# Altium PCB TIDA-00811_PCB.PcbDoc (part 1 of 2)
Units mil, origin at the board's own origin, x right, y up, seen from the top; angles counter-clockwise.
Board outline 3346.46 x 1968.5 mil, 2 copper layers (Top Layer, Bottom Layer), stack 62 mil thick; 221 components, 100 nets, 529 pads, 192 vias.
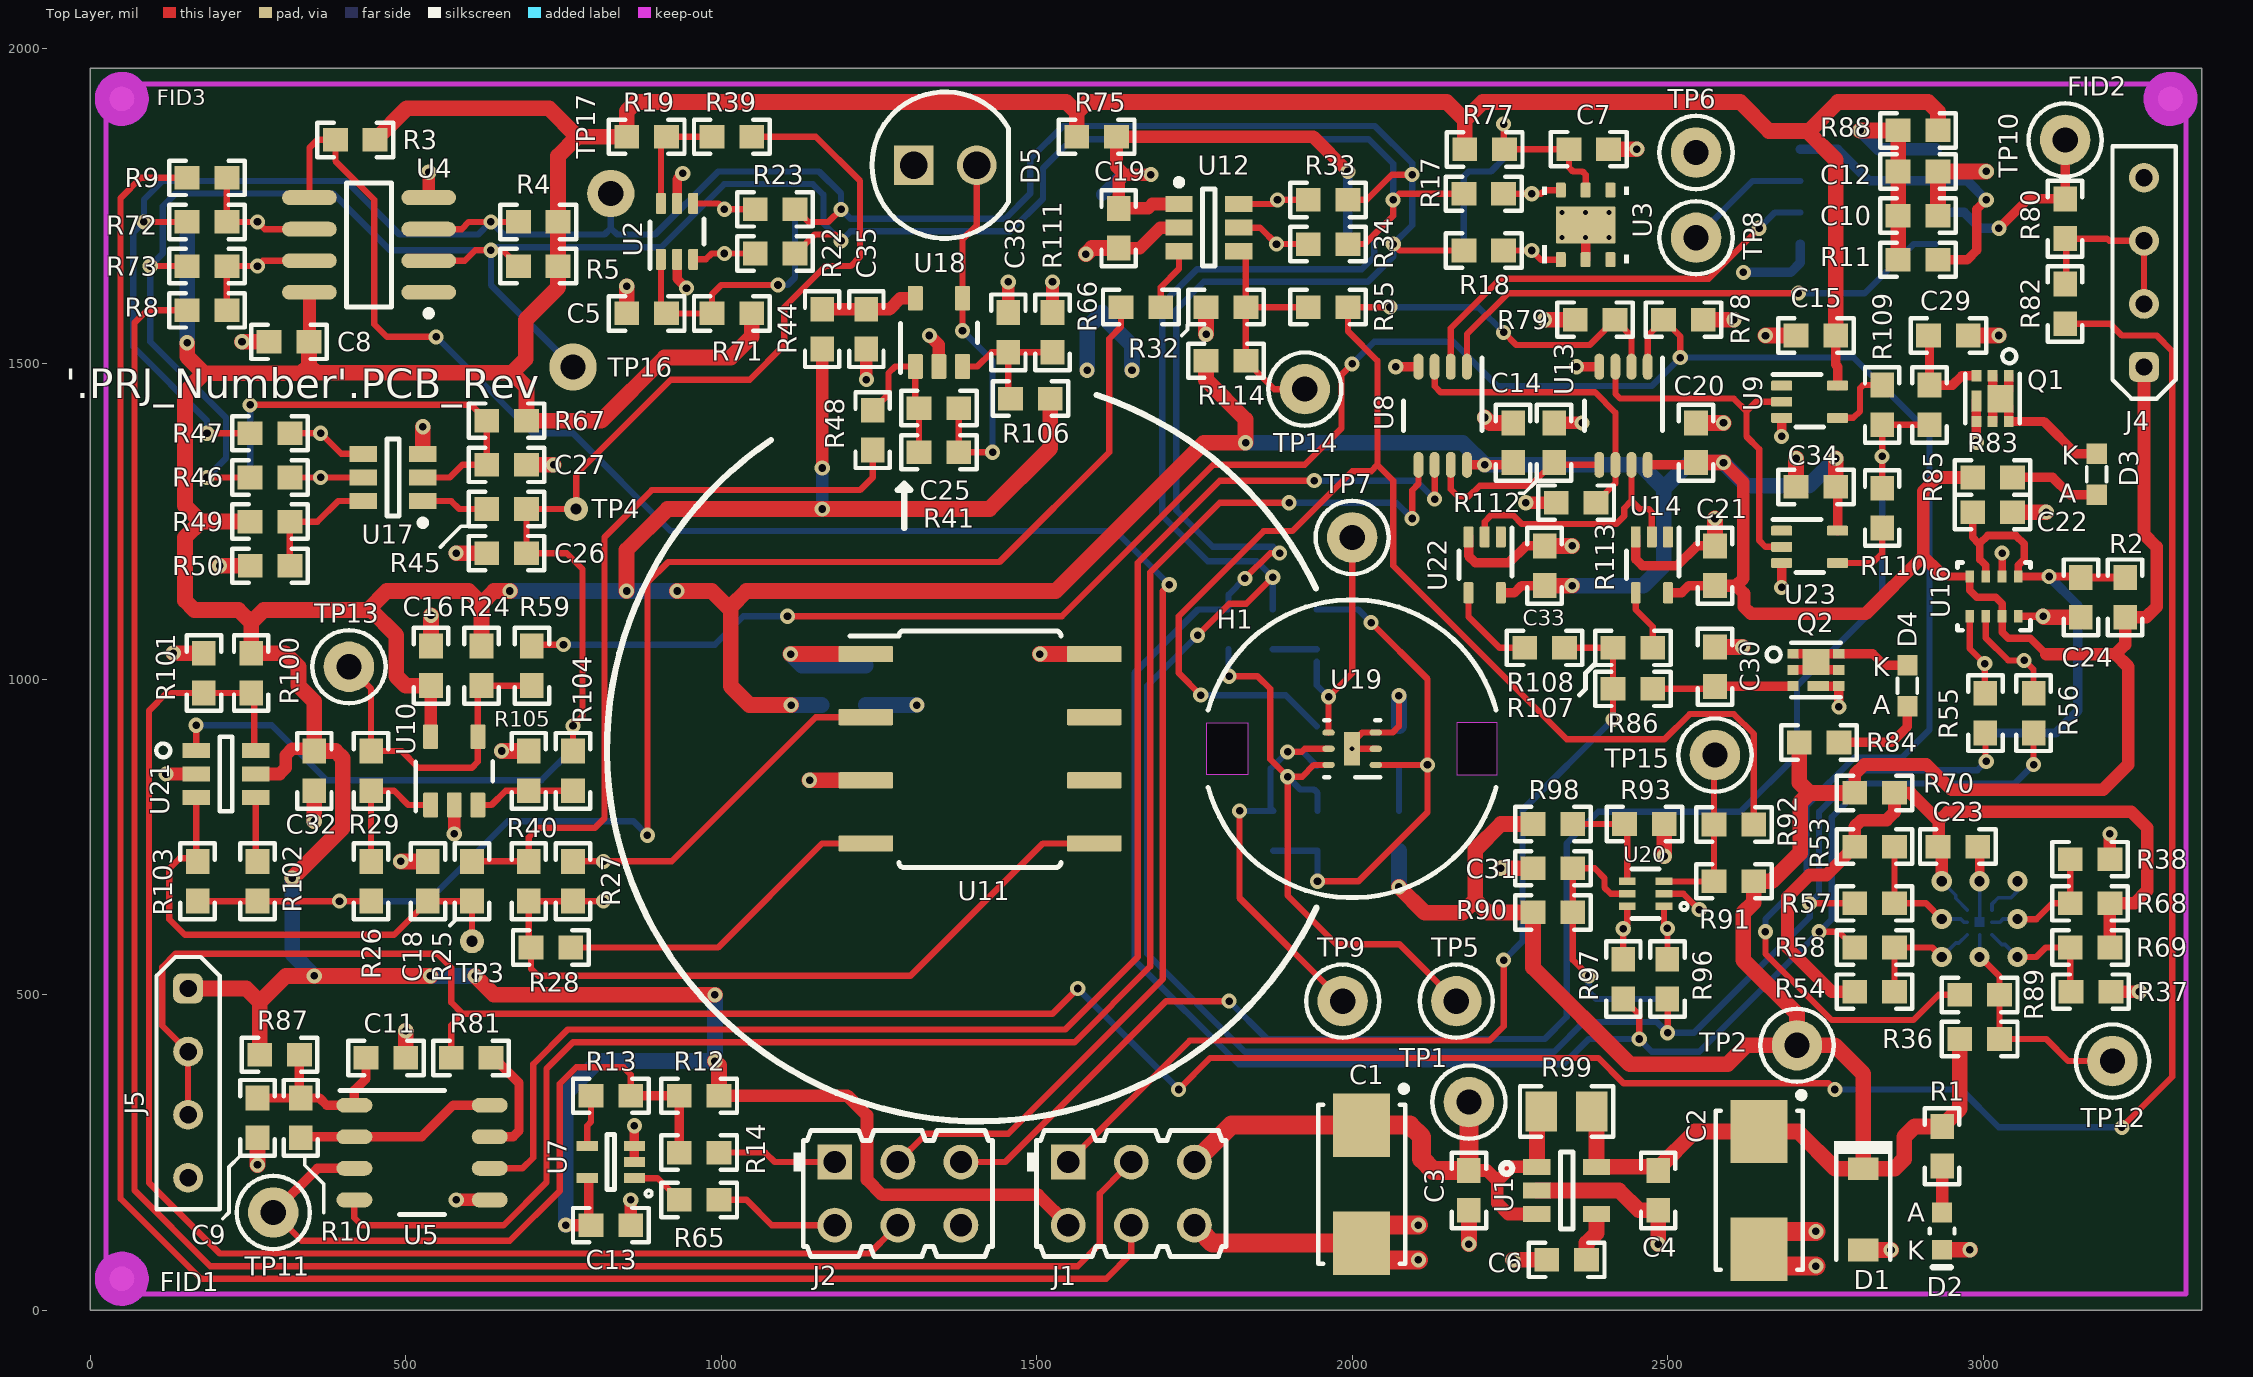
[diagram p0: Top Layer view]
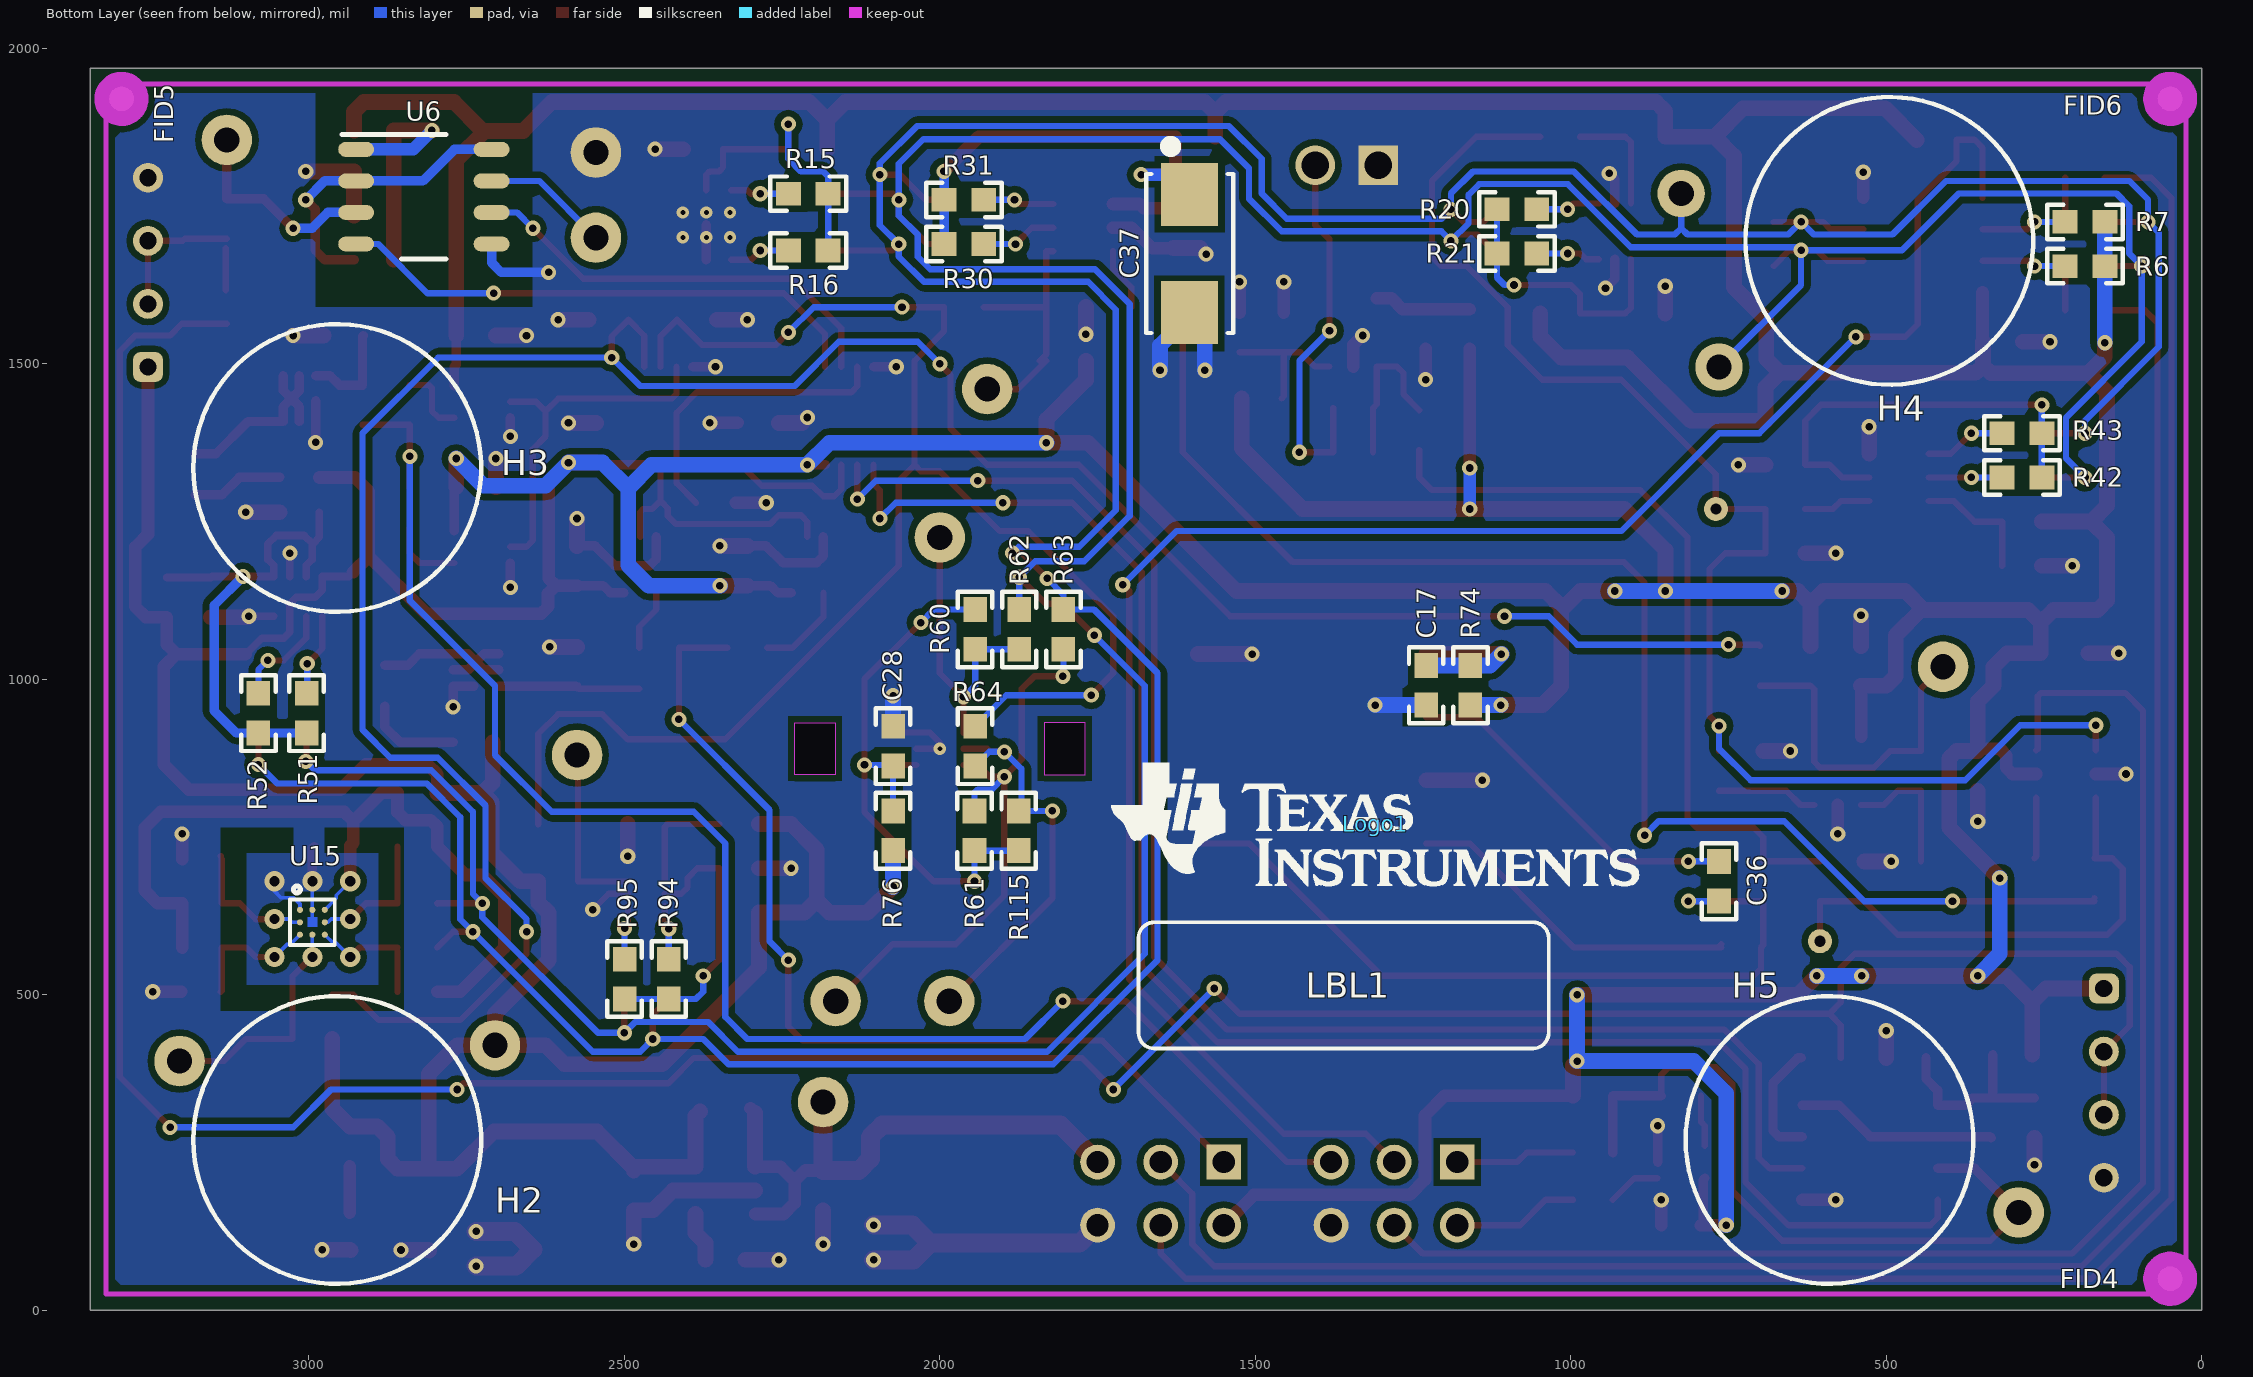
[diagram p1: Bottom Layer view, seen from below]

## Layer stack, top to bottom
Top Solder: solder mask 0.4, Solder Resist, Dk 3.5
Top Layer: signal copper 1.4
Dielectric1: core 59.2, FR-4 High Tg, Dk 4.8
Bottom Layer: signal copper 1.4
Bottom Solder: solder mask 0.4, Solder Resist, Dk 3.5

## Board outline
0,0 0,1968.5 3346.46,1968.5 3346.46,0

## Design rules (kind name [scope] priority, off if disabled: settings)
AcuteAngle [All] p1: minimum=4.50000000000000E+0001 checktracksonly=FALSE
AssemblyTestPointUsage [All] p1: valid=2
Clearance Clearance_1 [All] p1: gap=10 except(7.87: SMDPad-SMDPad)
Clearance Clearance_Trace [inpolygon vs istrack] p2: gap=15 except(7.87: SMDPad-SMDPad)
Clearance Clearance_Poly [InPolygon] p3: gap=25 except(15: Track-Poly Via-Poly)
Clearance [All] p4: gap=7.87
ComponentClearance ComponentClearance_MountingHoles_FiducialMarks [InComponentClass('Mounting Holes') vs InComponentClass('FiducialMark')] p1: gap=50 collisioncheckmode=3 verticalgap=10 showdistances=FALSE
ComponentClearance ComponentClearance_Shunt [InComponentClass('Header') vs InComponentClass('Shunt')] p2: gap=0 collisioncheckmode=3 verticalgap=0 showdistances=FALSE
ComponentClearance ComponentClearance_Logo [InComponentClass('Logo')] p3: gap=50 collisioncheckmode=3 verticalgap=10 showdistances=FALSE
ComponentClearance ComponentClearance_ScrewToNut [(HasFootprint('NY PMS 440 0025 PH')) vs (HasFootprint('Keystone_1902C'))] p4: gap=5 collisioncheckmode=3 verticalgap=10 showdistances=FALSE
ComponentClearance ComponentClearance_MountingHoles [InComponentClass('Mounting Holes')] p5: gap=250 collisioncheckmode=3 verticalgap=100000 showdistances=FALSE
ComponentClearance ComponentClearance_SmallPassives [HasFootprint('0201*') or HasFootprint('0402*') or HasFootprint('0508') or HasFootprint('0603*') or HasFootprint('0612') or HasFootprint('0805*') or HasFootprint('0815*') or HasFootprint('0830*') or HasFootprint('1206*') or HasFootprint('1210*') or HasFootprint('1808*') or HasFootprint('1812*') or HasFootprint('1825*') or HasFootprint('2010*') or HasFootprint('2220*') or HasFootprint('2225*') or HasFootprint('2512*') or HasFootprint('2728*') or HasFootprint('3518*') vs HasFootprint('0201*') or HasFootprint('0402*') or HasFootprint('0508') or HasFootprint('0603*') or HasFootprint('0612') or HasFootprint('0805*') or HasFootprint('0815*') or HasFootprint('0830*') or HasFootprint('1206*') or HasFootprint('1210*') or HasFootprint('1808*') or HasFootprint('1812*') or HasFootprint('1825*') or HasFootprint('2010*') or HasFootprint('2220*') or HasFootprint('2225*') or HasFootprint('2512*') or HasFootprint('2728*') or HasFootprint('3518*')] p6: gap=14.96 collisioncheckmode=3 verticalgap=10 showdistances=FALSE
ComponentClearance ComponentClearance_THtoSMT [IsThruComponent vs IsSMTComponent] p7: gap=40 collisioncheckmode=3 verticalgap=30 showdistances=FALSE
ComponentClearance ComponentClearance_THtoTH [IsThruComponent vs IsThruComponent] p8: gap=30 collisioncheckmode=3 verticalgap=30 showdistances=FALSE
ComponentClearance [All] p9: gap=30 collisioncheckmode=3 verticalgap=10 showdistances=FALSE
DiffPairsRouting [All] p1: maxlimit=100 minlimit=10 mostfreqgap=10 toplayer_minwidth=15 toplayer_maxwidth=15 toplayer_prefwidth=15 bottomlayer_minwidth=15 bottomlayer_maxwidth=15 bottomlayer_prefwidth=15 maxuncoupledlength=1000
FabricationTestPointUsage TestPointUsage [All] p1: valid=2 allowmultiple=FALSE
FabricationTestpoint Testpoint [All] p1: side=3 testpointundercomponent=TRUE minsize=40 maxsize=100 preferedsize=60 minholesize=0 maxholesize=40 preferedholesize=32 testpointgrid=1 allowsidetop=TRUE allowsidebottom=TRUE usegrid=TRUE gridtolerance=0.01
FanoutControl Fanout_LCC [IsLCC] p1: bgadir=Out bgaviamode=Centered fanoutstyle=Auto fanoutdirection=Alternating viagrid=1 // Fanout_LCC (Default Rule)
FanoutControl Fanout_BGA [IsBGA] p2: bgadir=Out bgaviamode=Centered fanoutstyle=Auto fanoutdirection=Alternating viagrid=1 // Fanout_BGA (Default Rule)
FanoutControl Fanout_Default [All] p4: bgadir=Out bgaviamode=Centered fanoutstyle=Auto fanoutdirection=Alternating viagrid=1 // Fanout_Default (Default Rule)
FanoutControl Fanout_Small [(CompPinCount < 5)] p5: bgadir=Out bgaviamode=Centered fanoutstyle=Auto fanoutdirection=OutThenIn viagrid=1 // Fanout_Small (Default Rule)
HoleSize [All] p1: absolutevalues=TRUE maxlimit=251 minlimit=7.87 maxpercent=80.000 minpercent=20.000
MinimumAnnularRing MinimumAnnularRing_ThermalPadVias [IsVia and InAnyComponent] p1: minimumring=5.91
MinimumAnnularRing [All] p2: minimumring=6
MinimumSolderMaskSliver MinimumSolderMaskSliver_Logo [InComponentClass('Logo') vs InComponentClass('Logo')] p1: minsoldermaskwidth=0.7
MinimumSolderMaskSliver [All] p2: minsoldermaskwidth=3
PlaneConnect [All] p1: planeconnectstyle=Relief reliefexpansion=10 reliefentries=4 reliefconductorwidth=10 reliefairgap=10
PolygonConnect [All] p1: connectstyle=Direct reliefconductorwidth=10 reliefentries=4 polygonreliefangle="90 Angle" airgapwidth=10
RoutingVias ThermalPadVias [IsVia and InAnyComponent] p1: holewidth=7.87 width=19.68 viastyle="Through Hole" minholewidth=7.87 minwidth=19.68 maxholewidth=12.99 maxwidth=23.62
RoutingVias [All] p2: holewidth=12 width=24 viastyle="Through Hole" minholewidth=12 minwidth=24 maxholewidth=20 maxwidth=40
SilkToSilkClearance SilkToSilkClearance_Pb-FreeLogo [(HasFootprint('Pb-Free_Overlay_Medium') OR HasFootprint('Pb-Free_Overlay_Small')) vs (HasFootprint('Pb-Free_Overlay_Medium') OR HasFootprint('Pb-Free_Overlay_Small'))] p1: silktosilkclearance=0
SilkToSilkClearance [All] p2: silktosilkclearance=1
SilkToSolderMaskClearance SilkToComponentPadClearance [IsPad and InAnycomponent] p1: minsilkscreentomaskgap=5 clearancetoexposedcopper=TRUE
SilkToSolderMaskClearance "Silk to Solder Mask Opening" [IsPad] p2: minsilkscreentomaskgap=4 clearancetoexposedcopper=TRUE
SolderMaskExpansion [All] p1: expansion=1.97
Width [All] p1: maxlimit=100 minlimit=6 preferedwidth=10 checkconnectedcopper=TRUE
16 further rules are at their usual default settings.

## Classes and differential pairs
component class TIDA-00811_Pg6: C9 C10 C11 C12 C13 C14 C15 C22 C24 C29 C34 D3 J4 J5 Q1 R2 R10 R11 R12 R13 R14 R51 R52 R55 R56 R65 R80 R81 R82 R83 R85 R87 R88 R109 R110 R112 R113 TP8 TP10 TP11 U5 U6 U7 U8 U9 U16 U23
component class Logo: Logo1
component class TIDA-00811_Pg7_EVM_Hardware: FID1 FID2 FID3 FID4 FID5 FID6 H1 H2 H3 H4 H5 LBL1 Logo1 ZZ1 ZZ2 ZZ3 ZZ4
component class FiducialMark: FID1 FID2 FID3 FID4 FID5 FID6
component class AssemblyNote: ZZ1 ZZ2 ZZ3 ZZ4
component class Label: LBL1
component class Header: J1 J2 J4 J5
component class TIDA-00811_Pg4: C5 C8 C16 C17 C18 C19 C25 C26 C27 C32 C35 C36 C37 C38 D5 J1 J2 R3 R4 R5 R6 R7 R8 R9 R19 R20 R21 R22 R23 R24 R25 R26 R27 R28 R29 R30 R31 R32 R33 R34 R35 R39 R40 R41 R42 R43 R44 R45 R46 R47 R48 R49 R50 R59 R66 R67 R71 R72 R73 R74 R75 R100 R101 R102 R103 R104 R105 R106 R111 R114 TP3 TP4 TP13 TP14 TP16 TP17 U2 U4 U10 U11 U12 U17 U18 U21
component class TIDA-00811_Pg5: C1 C2 C3 C4 C6 C7 C20 C21 C23 C28 C30 C31 C33 D1 D2 D4 Q2 R1 R15 R16 R17 R18 R36 R37 R38 R53 R54 R57 R58 R60 R61 R62 R63 R64 R68 R69 R70 R76 R77 R78 R79 R84 R86 R89 R90 R91 R92 R93 R94 R95 R96 R97 R98 R99 R107 R108 R115 TP1 TP2 TP5 TP6 TP7 TP9 TP12 TP15 U1 U3 U13 U14 U15 U19 U20 U22

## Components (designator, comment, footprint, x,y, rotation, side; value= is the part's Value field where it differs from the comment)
C1 "293D106X9025C2TE3" 6032-28 2015,200 r270 top
C2 "293D106X9025C2TE3" 6032-28 2645,190 r270 top
C3 "06033C104JAT2A" 0603#1 2185,190 r90 top
C4 "06033C104JAT2A" 0603#2 2485,190 r270 top
C5 "06033C104JAT2A" 0603#2 881.85,1580 r0 top
C6 "C1608C0G1E103J080AA" 0603#2 2340,80 r180 top
C7 "06033C104JAT2A" 0603#2 2375,1840.32 r180 top
C8 "06033C104JAT2A" 0603#2 315,1535 r180 top
C9 "06033C104JAT2A" 0603#2 265,305 r270 top
C10 "06033C104JAT2A" 0603#2 2896.85,1735 r0 top
C11 "06033C104JAT2A" 0603#2 468.5,400 r180 top
C12 "06033C104JAT2A" 0603#2 2896.85,1805 r180 top
C13 "06033C104JAT2A" 0603#2 825,135 r180 top
C14 "06033C104JAT2A" 0603#2 2255,1375 r270 top
C15 "06033C104JAT2A" 0603#2 2735,1544.93 r0 top
C16 "06033C104JAT2A" 0603#2 540,1021.5 r270 top
C17 "06033C104JAT2A" 0603#2 1229.09,990.67 r90 bottom
C18 "C1608C0G1E103J080AA" 0603#2 535,680 r270 top
C19 "06033C104JAT2A" 0603#2 1630,1715 r90 top
C20 "06033C104JAT2A" 0603#2 2545,1375 r270 top
C21 "06033C104JAT2A" 0603#2 2575,1180 r270 top
C22 "06033C104JAT2A" 0603#2 3015,1265 r180 top
C23 "06033C104JAT2A" 0603#2 2960,735 r180 top
C24 "06033C104JAT2A" 0603#2 3155,1130 r90 top
C25 "06035A2R7CAT2A" 0603#2 1345,1430 r0 top
C26 "C1608C0G1E103J080AA" 0603#2 659.84,1200 r0 top
C27 "" 0603#2 659.84,1340 r0 top
C28 "06033C104JAT2A" 0603#2 2074.09,894.17 r270 bottom
C29 "06033C104JAT2A" 0603#2 2945,1545 r0 top
C30 "06033C104JAT2A" 0603#2 2575,1020 r90 top
C31 "06033C104JAT2A" 0603#2 2318.15,700.62 r0 top
C32 "" 0603#2 355,855 r270 top
C33 "06033C104JAT2A" 0603#2 2305,1180 r270 top
C34 "06033C104JAT2A" 0603#2 2735,1305 r0 top
C35 "06033C104JAT2A" 0603#2 1230,1555 r90 top
C36 "GRM1885C1H560JA01D" 0603#2 765,680 r90 bottom
C37 "293D106X9025C2TE3" 6032-28 1604,1675 r270 bottom
C38 "C0603C105K4PACTU" 0603#2 1455,1550 r90 top
D1 "MMSZ5227B-7-F" SOD-123 2810,160 r270 top
D2 "LG L29K-G2J1-24-Z" "LG L29K_GREEN" 2935,125.47 r270 top
D3 "LED_LG L29K-G2J1-24-Z" LED0603AA 3180,1325 r270 top
D4 "LED_LG L29K-G2J1-24-Z" LED0603AA 2880,990 r270 top
D5 "SFH 213" SFH_213 1355,1815 r0 top
FID1 "Fiducial" Fiducial10-20 50,50 r0 top
FID2 "Fiducial" Fiducial10-20 3296.85,1920 r0 top
FID3 "Fiducial" Fiducial10-20 50,1920 r0 top
FID4 "Fiducial" Fiducial10-20 50,50 r180 bottom
FID5 "Fiducial" Fiducial10-20 3296.85,1920 r180 bottom
FID6 "Fiducial" Fiducial10-20 50,1920 r180 bottom
H1 "IML-0669" Murata_IML-0669 2000,890 r0 top
H2 "SJ-5303 (CLEAR)" Bumpon_SJ5003Transparent#1 2955,270 r180 bottom locked
H3 "SJ-5303 (CLEAR)" Bumpon_SJ5003Transparent#1 2955,1335 r180 bottom locked
H4 "SJ-5303 (CLEAR)" Bumpon_SJ5003Transparent#1 495,1695 r180 bottom
H5 "SJ-5303 (CLEAR)" Bumpon_SJ5003Transparent#2 1140,270 r180 bottom
J1 "61300621121" Mill-Max_802-10-006-10-001000 1650,185 r0 top
J2 "61300621121" Mill-Max_802-10-006-10-001000 1280,185 r0 top
J4 "61300411121" Mill-Max_342-xx-104-00-592000 3255,1645 r90 top
J5 "61300411121" Mill-Max_342-xx-104-00-592000 155,360 r270 top
LBL1 "Size: 0.65\" x 0.20 \"" Label_650x200 1360,515 r180 bottom
Logo1 "Texas Instruments" TI_Stacked_Overlay_Small 1310,770 r180 bottom
Q1 "CSD17571Q2" SON_CSD17571Q2 3015,1445 r180 top
Q2 "CSD17571Q2" SON_CSD17571Q2 2735,1015 r270 top
R1 "RC0603FR-071KL" 0603#2 2935,260 r90 top
R2 "RC0603JR-070RL" 0603#2 3225,1130 r90 top
R3 "RC0603FR-074K7L" 0603#2 420,1855 r0 top
R4 "RC0603FR-074K7L" 0603#2 710,1725 r0 top
R5 "RC0603FR-074K7L" 0603#2 710,1655 r0 top
R6 "RC0603FR-074K7L" 0603#2 185,1655 r180 bottom
R7 "RC0603FR-074K7L" 0603#2 185,1725 r180 bottom
R8 "CRCW060310R0FKEA" 0603#2 185,1585 r180 top
R9 "CRCW060310R0FKEA" 0603#2 185,1795 r180 top
R10 "RC0603JR-070RL" 0603#2 333.5,305 r270 top
R11 "RC0603JR-070RL" 0603#2 2896.85,1665 r0 top
R12 "RC0603FR-073K3L" 0603#2 965,340 r0 top
R13 "RC0603FR-07100RL" 0603#2 825,340 r0 top
R14 "RC0603FR-07100RL" 0603#2 965,250 r180 top
R15 "RC0603FR-074K7L" 0603#2 2208.5,1769.68 r180 bottom
R16 "RC0603FR-074K7L" 0603#2 2208.5,1679.68 r180 bottom
R17 "CRCW060310R0FKEA" 0603#2 2208.5,1769.68 r180 top
R18 "CRCW060310R0FKEA" 0603#2 2208.5,1679.68 r180 top
R19 "RC0603FR-074K7L" 0603#2 881.85,1860 r0 top
R20 "RC0603FR-074K7L" 0603#2 1085.35,1745 r0 bottom
R21 "RC0603FR-074K7L" 0603#2 1085.35,1675 r0 bottom
R22 "CRCW060310R0FKEA" 0603#2 1085.35,1674.93 r0 top
R23 "CRCW060310R0FKEA" 0603#2 1085.35,1744.93 r0 top
R24 "RC0603FR-074K7L" 0603#2 620,1021.5 r90 top
R25 "CRCW0603100RFKEA" 0603#2 605,680 r270 top
R26 "CRCW060310K0FKEA" 0603#2 445,680 r90 top
R27 "RC0603FR-0747KL" 0603#2 765,680 r270 top
R28 "RC0603JR-070RL" 0603#2 730,575 r0 top
R29 "CRCW06031M00FKEA" 0603#2 445,855 r90 top
R30 "RC0603FR-074K7L" 0603#2 1961.85,1690 r0 bottom
R31 "RC0603FR-074K7L" 0603#2 1961.85,1760 r0 bottom
R32 "RC0603JR-070RL" 0603#2 1800,1590 r180 top
R33 "CRCW060310R0FKEA" 0603#2 1961.85,1759.93 r0 top
R34 "CRCW060310R0FKEA" 0603#2 1961.85,1689.93 r0 top
R35 "RC0603JR-070RL" 0603#2 1961.85,1590 r0 top
R36 "RC0603JR-072K2L" 0603#2 2994.51,429.97 r180 top
R37 "RC0603JR-070RL" 0603#2 3171,504.97 r180 top
R38 "RC0603JR-070RL" 0603#2 3169.51,714.97 r180 top
R39 "RC0603JR-070RL" 0603#2 1016.85,1860 r0 top
R40 "RC0603JR-070RL" 0603#2 695,680 r90 top
R41 "RG1608P-5362-B-T5" 0603#2 1345,1360 r180 top
R42 "RC0603FR-074K7L" 0603#2 284.84,1320 r180 bottom
R43 "RC0603FR-074K7L" 0603#2 284.84,1390 r180 bottom
R44 "RC0603JR-070RL" 0603#2 1160,1555 r270 top
R45 "RC0603JR-070RL" 0603#2 659.84,1270 r0 top
R46 "CRCW060310R0FKEA" 0603#2 284.84,1320 r0 top
R47 "CRCW060310R0FKEA" 0603#2 284.84,1390 r0 top
R48 "RC0603JR-070RL" 0603#2 1240,1395 r270 top
R49 "RC0603FR-074K7L" 0603#2 284.84,1250 r0 top
R50 "RC0603JR-070RL" 0603#2 285,1180 r0 top
R51 "RC0603FR-074K7L" 0603#2 3003.63,946.5 r270 bottom
R52 "RC0603FR-074K7L" 0603#2 3080,946.5 r270 bottom
R53 "RC0603FR-074K7L" 0603#2 2828.01,735 r180 top
R54 "RC0603FR-074K7L" 0603#2 2828.01,504.97 r180 top
R55 "CRCW060310R0FKEA" 0603#2 3003.63,946.5 r90 top
R56 "CRCW060310R0FKEA" 0603#2 3080,946.5 r90 top
R57 "CRCW060310R0FKEA" 0603#2 2828.01,644.97 r0 top
R58 "CRCW060310R0FKEA" 0603#2 2828.01,574.97 r0 top
R59 "RC0603JR-070RL" 0603#2 700,1021.5 r90 top
R60 "RC0603FR-074K7L" 0603#2 1944.09,1079.17 r90 bottom
R61 "RC0603FR-074K7L" 0603#2 1945,760 r270 bottom
R62 "CRCW060310R0FKEA" 0603#2 1874.09,1079.17 r90 bottom
R63 "CRCW060310R0FKEA" 0603#2 1804.09,1079.17 r90 bottom
R64 "RC0603JR-070RL" 0603#2 1944.09,894.17 r90 bottom
R65 "RC0603JR-070RL" 0603#2 965,175 r0 top
R66 "RC0603JR-070RL" 0603#2 1665,1590 r180 top
R67 "RC0603JR-070RL" 0603#2 659.84,1410 r0 top
R68 "RC0603FR-074K7L" 0603#2 3169.51,644.97 r0 top
R69 "RC0603FR-074K7L" 0603#2 3169.51,574.97 r0 top
R70 "RC0603JR-070RL" 0603#2 2828.01,820 r180 top
R71 "RC0603JR-070RL" 0603#2 1016.85,1580 r0 top
R72 "RC0603JR-070RL" 0603#2 185,1725 r180 top
R73 "RC0603JR-070RL" 0603#2 185,1655 r180 top
R74 "RC0603JR-070RL" 0603#2 1159.09,990.67 r270 bottom
R75 "RC0603JR-070RL" 0603#2 1595,1860 r180 top
R76 "RC0603JR-070RL" 0603#2 2074.09,760 r270 bottom
R77 "RC0603JR-070RL" 0603#2 2210,1840 r180 top
R78 "RC0603FR-074K7L" 0603#2 2525,1570 r0 top
R79 "RC0603FR-074K7L" 0603#2 2385,1570.07 r180 top
R80 "RC0603JR-070RL" 0603#2 3130,1730 r90 top
R81 "RC0603JR-070RL" 0603#2 603.5,400 r180 top
R82 "RC0603JR-070RL" 0603#2 3130,1595 r90 top
R83 "CRCW0603300RJNEA" 0603#2 3015,1320 r180 top
R84 "CRCW0603300RJNEA" 0603#2 2740,900 r180 top
R85 "CRCW0603300RJNEA" 0603#2 2915,1435 r90 top
R86 "CRCW0603300RJNEA" 0603#2 2445,985 r0 top
R87 "RC0603JR-070RL" 0603#2 300,405 r0 top
R88 "RC0603JR-070RL" 0603#2 2896.85,1870 r180 top
R89 "RC0603JR-070RL" 0603#2 2994.51,499.97 r180 top
R90 "RC0603JR-070RL" 0603#2 2318.15,630.68 r180 top
R91 "CRCW060310K0JNEA" 0603#2 2605,680 r0 top
R92 "RC0603JR-070RL" 0603#2 2605,770 r0 top
R93 "RC0603JR-070RL" 0603#2 2463.15,770.68 r0 top
R94 "RC0603FR-074K7L" 0603#2 2429.65,525 r270 bottom
R95 "RC0603FR-074K7L" 0603#2 2499.65,525 r270 bottom
R96 "CRCW060310R0FKEA" 0603#2 2499.65,525 r270 top
R97 "CRCW060310R0FKEA" 0603#2 2429.65,525 r270 top
R98 "RC0603FR-074K7L" 0603#2 2318.15,770.75 r180 top
R99 "CRCW08050000Z0EA" 0805_HV 2340,315 r0 top
R100 "RC0603FR-074K7L" 0603#2 255,1010 r270 top
R101 "RC0603FR-074K7L" 0603#2 180,1010 r270 top
R102 "ERJ-3GEY0R00V" 0603#2 265,680 r90 top
R103 "ERJ-3GEY0R00V" 0603#2 170,680 r270 top
R104 "CRCW0603300RJNEA" 0603#2 765.07,855 r90 top
R105 "CRCW060310K0FKEA" 0603#2 695,855 r90 top
R106 "CRCW060313K7FKEA" 0603#2 1490,1445 r180 top
R107 "RC0603JR-070RL" 0603#2 2445,1050 r180 top
R108 "RC0603JR-070RL" 0603#2 2305,1050 r0 top
R109 "RC0603JR-070RL" 0603#2 2840,1435 r270 top
R110 "RC0603JR-070RL" 0603#2 2840.07,1271.5 r90 top
R111 "RC0603FR-07280RL" 0603#2 1525,1550 r270 top
R112 "RC0603JR-070RL" 0603#2 2320,1375 r90 top
R113 "RC0603JR-070RL" 0603#2 2355,1280 r0 top
R114 "RC0603FR-074K7L" 0603#2 1800,1505 r180 top
R115 "RC0603FR-074K7L" 0603#2 1875,760 r270 bottom
TP1 "5000" Keystone5000 2185,330 r0 top
TP2 "5000" Keystone5000 2705,420 r0 top
TP3 "TESTPOINT" TP_H045P075 605,585 r0 top
TP4 "TESTPOINT" TP_H045P075 770,1270 r270 top
TP5 "5000" Keystone5000 2165,490 r0 top
TP6 "5000" Keystone5000 2545,1835 r0 top
TP7 "5000" Keystone5000 2000,1225 r0 top
TP8 "5000" Keystone5000 2545,1700 r0 top
TP9 "5000" Keystone5000 1985,490 r0 top
TP10 "5000" Keystone5000 3130,1855 r0 top
TP11 "5000" Keystone5000 290,155 r0 top
TP12 "5000" Keystone5000 3205,395 r0 top
TP13 "5000" Keystone5000 410,1020 r0 top
TP14 "5000" Keystone5000 1925,1460 r0 top
TP15 "5000" Keystone5000 2575,880 r0 top
TP16 "TP-5001-BLACK" TH-40 765,1495 r270 top
TP17 "TP-5001-BLACK" TH-40 825,1770 r90 top
U1 "LP2985-33DBVR" DBV0005A_N#1 2340,190 r0 top
U2 "TPL0401A-10DCKR" DCK0006A_N 930,1710 r90 top
U3 "HDC1080DMBR" DMB0006A 2370,1720.32 r90 top
U4 "PCA9515ADR" D0008A_N#1 441.85,1688.5 r180 top
U5 "TMP107BIDR" D0008A_N#2 525.79,250 r0 top
U6 "TMP107BIDR" D0008A_N#2 2817.72,1765 r180 bottom
U7 "SN74LVC1G125DCKR" DCK0005A_N#1 825,235 r180 top
U8 "SN74LVC2G32DCTR" DCT0008A_N 2143.46,1417.76 r270 top
U9 "SN74LVC1G14DCKR" DCK0005A_N#2 2725,1440 r0 top
U10 "LMV331IDBVR" DBV0005A_N#2 576.85,855 r90 top
U11 "OPT101P-J" DTL0008A_N 1410.2,890 r0 top
U12 "ADC101C021CIMK/NOPB" MK06A_N 1772.76,1715.98 r0 top
U13 "SN74LVC2G32DCTR" DCT0008A_N 2430,1417.76 r270 top
U14 "SN74LVC1G14DCKR" DCK0005A_N#2 2475,1181.5 r270 top
U15 "TMP007AIYZFR" YZF0008AEAE 2994.51,614.97 r180 bottom
U16 "BMP280" LGA8-2X2_5MM_0_65 3017.2,1131.5 r180 top
U17 "DAC101C081CIMK" MK06A_N 479.84,1320 r180 top
U18 "OPA320AIDBVR" DBV0005A_N#2 1345,1550 r90 top
U19 "OPT3001DNPT" DNP0006A 2000,890 r180 top
U20 "TMP102AIDRLT" DRL0006A_N 2465,660 r180 top
U21 "SN74LVC1G3157DBVR" SOT23-6 215,850 r0 top
U22 "SN74LVC1G17DCKR" DCK0005A_N#2 2210,1181.5 r270 top
U23 "SN74LVC1G17DCKR" DCK0005A_N#2 2725,1210 r0 top
ZZ1 "This Assembly Note is for PCB labels only" AssemblyNoteLabel -48.15,2846 r0 top
ZZ2 "These assemblies are ESD sensitive, ESD precautions shall be observed." AssemblyNote -48.15,2737.11 r0 top
ZZ3 "These assemblies must be clean and free from flux and all contaminants. Use of no clean flux is not acceptable." AssemblyNote -48.15,2648.56 r0 top
ZZ4 "These assemblies must comply with workmanship standards IPC-A-610 Class 2, unless otherwise specified." AssemblyNote -48.15,2560 r0 top

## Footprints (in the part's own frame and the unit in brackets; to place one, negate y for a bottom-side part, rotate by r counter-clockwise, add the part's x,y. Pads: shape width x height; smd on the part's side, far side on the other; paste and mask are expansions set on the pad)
0603#1 [mm] "0603 from SM-752 data"
  rect 1x0.95 smd: 1(0.8,0) 2(-0.8,0)
  silkscreen extent -1.52,-0.69 1.52,0.69, body extent -0.87,-0.47 0.87,0.47, height 1
0603#2 [mm] "0603 from SM-752 data"
  rect 1x0.95 smd: 1(-0.8,0) 2(0.8,0)
  silkscreen extent -1.52,-0.69 1.52,0.69, body extent -0.87,-0.47 0.87,0.47, height 1
0805_HV [mil] "0805 with 30mil clearance between pads"
  rect 50x63 smd: 1(-40,0) 2(40,0)
  silkscreen extent -74,-40 74,40, body extent -43,-29 43,29, height 57
6032-28 [mm] "Medium Density IPC based on Vishay Sprague 293D datasheet."
  rect 2.55x2.3 smd: 1(-2.375,0) 2(2.375,0)
  silkscreen extent -3.96,-1.75 3.2,1.83, body extent -3.15,-1.75 3.15,1.75, height 2.8
AssemblyNote [mil] "Assembly Note"
AssemblyNoteLabel [mil] "Assembly Note for PCB Labels"
Bumpon_SJ5003Transparent#1 [mil] "3M Hemispherical Bumpon transparent"
  round 1 on Mech4: 0(0,0)
  silkscreen extent -228,-228 228,228, body extent -219,-218 219,218, height 197
Bumpon_SJ5003Transparent#2 [mil] "3M Hemispherical Bumpon transparent"
  round 1 on Mech4: 0(550,0)
  silkscreen extent 322,-228 778,228, body extent 331,-218 769,218, height 197
D0008A_N#1 [mm] "SOIC, 8-Leads, Body 4.9x3.9mm, Pitch 1.27mm, IPC Medium Density"
  oval 2.2x0.6 smd: 1(-2.4,1.905) 2(-2.4,0.635) 3(-2.4,-0.635) 4(-2.4,-1.905) 5(2.4,-1.905) 6(2.4,-0.635) 7(2.4,0.635) 8(2.4,1.905)
  silkscreen extent -2.53,-2.5 0.9,2.88, body extent -2,-2.5 2,2.5, height 1.75
D0008A_N#2 [mm] "SOIC, 8-Leads, Body 4.9x3.9mm, Pitch 1.27mm, IPC Medium Density"
  oval 1.45x0.6 smd: 1(-2.725,1.905) 2(-2.725,0.635) 3(-2.725,-0.635) 4(-2.725,-1.905) 5(2.725,-1.905) 6(2.725,-0.635) 7(2.725,0.635) 8(2.725,1.905)
  silkscreen extent -3.3,-2.5 0.9,2.5, body extent -3,-2.45 3,2.45, height 1.63
DBV0005A_N#1 [mm] "SOT23, 5-Leads, Body 2.9x1.6mm, Pitch 0.95mm, Lead Span 2.8mm, IPC Medium Density"
  rect 1.1x0.65 smd: 1(-1.2,0.95) 2(-1.2,0) 3(-1.2,-0.95) 4(1.2,-0.95) 5(1.2,0.95)
  silkscreen extent -0.25,-1.55 0.25,1.55, body extent -1.42,-1.46 1.42,1.46, height 1.08
DBV0005A_N#2 [mm] "SOT23, 5-Leads, Body 2.9x1.6mm, Pitch 0.95mm, Lead Span 2.8mm, IPC Medium Density"
  rrect17% 1x0.6 smd: 1(-1.375,0.95) 2(-1.375,0) 3(-1.375,-0.95) 4(1.375,-0.95) 5(1.375,0.95)
  silkscreen extent -1.63,-1.55 0.38,1.55, body extent -1.42,-1.46 1.42,1.46, height 1.09
DCK0005A_N#1 [mm] "SOT353, 5-Leads, Body 2x1.3mm, Pitch 0.65mm, Lead Span 2.1mm, IPC Medium Density"
  rect 0.85x0.4 smd: 1(-0.95,0.65) 2(-0.95,0) 3(-0.95,-0.65) 4(0.95,-0.65) 5(0.95,0.65)
  silkscreen extent -0.15,-1.1 0.15,1.1, body extent -1.14,-1 1.14,1, height 0.94
DCK0005A_N#2 [mm] "SOT353, 5-Leads, Body 2x1.3mm, Pitch 0.65mm, Lead Span 2.1mm, IPC Medium Density"
  rrect25% 0.85x0.4 smd: 1(-1.125,0.65) 2(-1.125,0) 3(-1.125,-0.65) 4(1.125,-0.65) 5(1.125,0.65)
  silkscreen extent -1.48,-1.02 0.55,1.1, body extent -1.14,-1 1.14,1, height 0.95
DCK0006A_N [mm] "SOT23, 6-Leads, Body 2x1.3mm, Pitch 0.65mm, Lead Span 2.1mm, IPC Medium Density"
  rrect25% 0.85x0.4 smd: 1(-1.125,0.65) 2(-1.125,0) 3(-1.125,-0.65) 4(1.125,-0.65) 5(1.125,0) 6(1.125,0.65)
  silkscreen extent -1.5,-1.09 0.51,1.09, body extent -1.14,-1 1.14,1, height 0.95
DCT0008A_N [mm] "TSOP, 8-Leads, Body 3x2.8mm, Pitch 0.65mm, IPC Medium Density"
  oval 1.05x0.4 smd: 1(-1.975,0.975) 2(-1.975,0.325) 3(-1.975,-0.325) 4(-1.975,-0.975) 5(1.975,-0.975) 6(1.975,-0.325) 7(1.975,0.325) 8(1.975,0.975)
  silkscreen extent -2.32,-1.57 0.6,1.58, body extent -2.01,-1.47 2.01,1.48, height 1.3
DMB0006A [mm] "TI"
  rrect25% 0.6x0.4 smd: 1(-1.4,1) 2(-1.4,0) 3(-1.4,-1) 4(1.4,-1) 5(1.4,0) 6(1.4,1)
  rrect7% 1.5x2.4 smd paste-0.75: 7(0,0)
  silkscreen extent -1.55,-1.75 1.55,1.75, body extent -1.5,-1.5 1.5,1.5, height 0.81
DNP0006A [mm] "DFN-6 2x2mm"
  oval 0.5x0.25 smd: 1(-0.95,0.65) 2(-0.95,0) 3(-0.95,-0.655) 4(0.95,-0.65) 5(0.95,0) 6(0.95,0.65)
  rect 0.65x1.35 smd paste-0.5: 7(0,0)
  silkscreen extent -1.12,-1.15 1.12,1.15, body extent -1,-1 1,1, height 0.64
DRL0006A_N [mm] "SOTFL, 6-Flat Leads, Body 1.2x1.6x0.6mm, Pitch 0.5mm, IPC Medium Density"
  rect 0.67x0.3 smd: 1(-0.74,0.5) 2(-0.74,0) 3(-0.74,-0.5) 4(0.74,-0.5) 5(0.74,0) 6(0.74,0.5)
  silkscreen extent -0.55,-1 0.55,1, body extent -0.65,-0.85 0.65,0.85, height 0.6
DTL0008A_N [mm] "SOP, 8-Leads, Body 9.53x6.52mm, Pitch 2.54mm, IPC Medium Density"
  rrect15% 2.2x0.65 smd: 1(-4.6,3.81) 2(-4.6,1.27) 3(-4.6,-1.27) 4(-4.6,-3.81) 5(4.6,-3.81) 6(4.6,-1.27) 7(4.6,1.27) 8(4.6,3.81)
  silkscreen extent -5.23,-4.78 3.25,4.75, body extent -5.12,-4.76 5.12,4.76, height 4.94
Fiducial10-20 [mm]
  round 1 smd mask+0.5: 1(0,0)
  Top Layer keep-out circle w1.178: c0,0 r0.5
Keystone5000 [mil] "For Keystone 500x miniature loop terminals"
  round 80 hole 40: 1(0,0)
  silkscreen extent -58,-58 58,58, body extent -49,-49 49,49, height 182
Label_650x200 [mil] "Thermal Transfer Label"
  silkscreen extent -325,-100 325,100, body extent -325,-100 325,100, height 1
LED0603AA [mil]
  rect 32x32 smd: 1(-32.48,0) 2(32.48,0)
  silkscreen extent -11,-16 11,16
"LG L29K_GREEN" [mm] "OSRAM"
  rect 0.8x0.8 smd: 1(-0.75,0) 2(0.75,0)
  silkscreen extent -0.1,-0.5 1.45,0.5, body extent -0.9,-0.45 0.9,0.45, height 0.67
LGA8-2X2_5MM_0_65 [mm] "LGA, 8-Leads, Body 2x2.5mm, Pitch 0.65mm"
  rect 0.35x0.5 smd: 1(-0.975,0.8) 2(-0.325,0.8) 3(0.325,0.8) 4(0.975,0.8) 5(0.975,-0.8) 6(0.325,-0.8) 7(-0.325,-0.8) 8(-0.975,-0.8)
  silkscreen extent -1.47,-1.36 1.47,1.36, body extent -1.3,-1.05 1.3,1.05, height 1.01
Mill-Max_342-xx-104-00-592000 [mm] "TH, 5-Leads, Body 400x100mil, Pitch 100mil"
  rrect50% 1.2x1.2 hole 0.7: 1(-3.81,0)
  round 1.2 hole 0.7: 2(-1.27,0) 3(1.27,0) 4(3.81,0)
  silkscreen extent -5.08,-1.27 5.08,1.27, body extent -5.08,-1.27 5.08,1.27, height 11.68
Mill-Max_802-10-006-10-001000 [mm] "Header, 2.54 mm, 3x2, TH"
  rect 1.4x1.4 hole 0.9: 1(-2.54,1.27)
  round 1.4 hole 0.9: 2(-2.54,-1.27) 3(0,1.27) 4(0,-1.27) 5(2.54,1.27) 6(2.54,-1.27)
  silkscreen extent -4.21,-2.54 3.81,2.54, body extent -3.85,-2.54 3.77,2.54, height 8.11
MK06A_N [mm] "SOT23, 6-Leads, Body 3.0x1.7mm, Pitch 0.95mm, Lead Span 2.9mm, IPC Medium Density"
  rect 1.1x0.65 smd: 1(-1.2,0.95) 2(-1.2,0) 3(-1.2,-0.95) 4(1.2,-0.95) 5(1.2,0) 6(1.2,0.95)
  silkscreen extent -1.32,-1.55 0.25,1.95, body extent -0.9,-1.55 0.9,1.55, height 1
Murata_IML-0669 [mil] "Pyroelectric Infrared Lens, TH"
  Keep-Out Layer board cut-out: 165.35,-41.34 230.31,-41.34 230.31,41.34 165.35,41.34
  Keep-Out Layer board cut-out: -165.35,-41.34 -230.32,-41.34 -230.32,41.34 -165.35,41.34
  silkscreen extent -228,-236 228,236, body extent -256,-236 256,236, height 335
SFH_213 [mm] "TH, 2-Leads, Dia 5.7mm, Pin Spacing 2.54mm"
  rect 1.6x1.6 hole 1.1: 1(-1.27,0)
  round 1.6 hole 1.1: 2(1.27,0)
  silkscreen extent -2.95,-2.95 2.55,2.95, body extent -2.95,-2.95 2.55,2.95, height 11.4
SOD-123 [mm] "On Semi recommended land pattern"
  rect 0.915x1.22 smd: 1(-1.637,0) 2(1.637,0)
  silkscreen extent -2.74,-1.17 2.03,1.17, body extent -1.93,-0.9 1.93,0.9, height 1.35
SON_CSD17571Q2 [mm] "SON, MOSFET, N-CH, 30V, 22A, SON 2X2 MM"
  rect 0.4x0.455 smd mask+0.038: 1(-0.65,-0.923) 2(0,-0.923) 5(0,0.923) 6(-0.65,0.923)
  rect 0.4x0.455 smd: 3(0.65,-0.923) 4(0.65,0.923)
  rect 0.4x0.85 smd mask+0.038: 7(0.65,0.096)
  rect 1.05x1.1 smd mask+0.038: 8(-0.325,0)
  silkscreen extent -1.1,-1.98 1.1,1, body extent -1,-1 1,0.97, height 0.85
SOT23-6 [mm] "IC DAC R-R LP 12BIT SOT23-6"
  rect 1.1x0.6 smd: 1(-1.2,0.95) 2(-1.2,0) 3(-1.2,-0.95) 4(1.2,-0.95) 5(1.2,0) 6(1.2,0.95)
  silkscreen extent -2.8,-1.5 0.25,1.5, body extent -0.8,-1.45 0.8,1.45, height 1.45
TH-40 [mil]
  round 75 hole 40: 1(0,0)
TI_Stacked_Overlay_Small [mil]
  silkscreen extent -418,-98 418,98
TP_H045P075 [mil] "TP_H0.45P0.75"
  round 38 hole 17.72: 1(0,0)
YZF0008AEAE [mm] "WCSP"
  round 0.245 smd paste-0.125: A1(-0.5,0.5) A2(0,0.5) A3(0.5,0.5) B1(-0.5,0) B3(0.5,0) C1(-0.5,-0.5) C2(0,-0.5) C3(0.5,-0.5)
  body extent -0.78,-0.78 0.78,0.78, height 0.63

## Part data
C1 C2 C37: "CAP, TA, 10 µF, 25 V, +/- 10%, 1.5 ohm, SMD"
C3 C4 C5 C7 C8 C9 C10 C11 C12 C13 C14 C15 C17 C19 C20 C21 C22 C23 C24 C28 C31 C33 C34 C35: "CAP, CERM, 0.1 µF, 25 V, +/- 5%, X7R, 0603"
C6: library part C1608C0G1E103J, "CAP, CERM, 0.01 µF, 25 V, +/- 5%, C0G/NP0, 0603"
C16 C29 C30: "CAP, CERM, 0.1uF, 25V, +/-5%, X7R, 0603"
C18 C26: library part C1608C0G1E103J, "CAP, CERM, 0.01uF, 25V, +/-5%, C0G/NP0, 0603"
C25: "CAP, CERM, 2.7 pF, 50 V,+/- 9%, C0G/NP0, 0603"
C27 C32: library part 06033C104JAT2A, "CAP, CERM, 0.1uF, 25V, +/-5%, X7R, 0603"
C36: "CAP, CERM, 56 pF, 50 V, +/- 5%, C0G/NP0, 0603"
C38: "CAP, CERM, 1 µF, 16 V,+/- 10%, X5R, 0603"
D1: "Diode, Zener, 3.6 V, 500 mW, SOD-123"
D2: "LED, Green, SMD"
D3 D4: "LED SmartLED Green 570NM"
D5: "Silicon PIN Photodiode, TH"
FID1 FID2 FID3 FID4 FID5 FID6: "Fiducial mark.  There is nothing to buy or mount."
H1: "Lens, Ceiling Mount, TH"
H2 H3 H4 H5: "Bumpon, Hemisphere, 0.44 X 0.20, Clear"
J1 J2: library part 802-10-006-10-001000, "Header, 2.54 mm, 3x2, Gold, TH"
J4 J5: library part 342-10-104-00-592000, "Header, 2.54mm, 4x1, Gold, TH"
LBL1: library part THT-14-423-10, "Thermal Transfer Printable Labels, 0.650\" W x 0.200\" H - 10,000 per roll"
Logo1: library part TI_Logo, "Texas Instrument Corporate Signature"
Q1 Q2: "MOSFET, N-CH, 30V, 22A, SON 2X2 MM"
R1: "RES, 1.00 k, 1%, 0.1 W, 0603"
R2 R10 R11 R28 R32 R35 R37 R38 R39 R40 R44 R45 R48 R50 R59 R64 R65 R66 R67 R70 R71 R72 R73 R74 R75 R76 R77 R80 R81 R82 R87 R88 R89 R90 R92 R93 R102 R103 R107 R108 R109 R110 R112 R113: "RES, 0, 5%, 0.1 W, 0603"
R3 R4 R5 R6 R7 R15 R16 R19 R20 R21 R24 R30 R31 R42 R43 R49 R51 R52 R53 R54 R60 R61 R68 R69 R78 R79 R94 R95 R98 R100 R101 R114 R115: "RES, 4.70 k, 1%, 0.1 W, 0603"
R8 R9 R17 R18 R22 R23 R33 R34 R46 R47 R55 R56 R57 R58 R62 R63 R96 R97: "RES, 10.0, 1%, 0.1 W, 0603"
R12: "RES, 3.30 k, 1%, 0.1 W, 0603"
R13 R14: "RES, 100, 1%, 0.1 W, 0603"
R25: "RES, 100 ohm, 1%, 0.1W, 0603"
R26 R105: library part RNCF0603TKY10K0, "RES, 10.0k ohm, 1%, 0.1W, 0603"
R27: "RES, 47.0 k, 1%, 0.1 W, 0603"
R29: "RES, 1.00Meg ohm, 1%, 0.1W, 0603"
R36: "RES, 2.2 k, 5%, 0.1 W, 0603"
R41: "RES, 53.6 k, 0.1%, 0.1 W, 0603"
R83 R84 R85 R86 R104: "RES, 300 ohm, 5%, 0.1W, 0603"
R91: "RES, 10 k, 5%, 0.1 W, 0603"
R99: "RES, 0, 5%, 0.125 W, 0805"
R106: "RES, 13.7 k, 1%, 0.1 W, 0603"
R111: "RES, 280, 1%, 0.1 W, 0603"
TP1 TP2 TP5 TP6 TP7 TP8 TP9 TP10 TP11 TP12 TP13 TP14 TP15: "Test Point, Miniature, Red, TH"
TP3 TP4: library part TP_H0.45P0.75, "Testpoint"
TP16 TP17: "Test Point,  Black, Thru Hole Color Keyed"
U1: "100-mA ULTRA-LOW DROPOUT REGULATOR WITH SHUTDOWN, DBV0005A"
U2: "128 TAPS Single Channel Digital Potentiometer with I2C Interface, DCK0006A"
U3: "Low Power, High Accuracy Digital Humidity Sensor with Temperature Sensor, DMB0006A"
U4: "Dual Bidirectional I2C Bus and SMBus Repeater, 2 Channel Width, 2.3 to 3.6 V, -40 to 85 degC, 8-pin SOIC (D), Green (RoHS & no Sb/Br)"
U5 U6: "TMP107B, D0008A"
U7: "Single Bus Buffer Gate With 3-State Output, DCK0005A"
U8 U13: "Dual 2-Input Positive-OR Gate, DCT0008A"
U9 U14: "SINGLE SCHMITT-TRIGGER INVERTER, DCK0005A"
U10: library part LMV331IDBV, "Single General Purpose Low-Voltage Comparator, DBV0005A"
U11: "Monolithic Photodiode and Single-Supply Transimpedance Amplifier, DTL0008A"
U12: "I2C-Compatible, 10-Bit Analog-to-Digital Converter (ADC) with Alert Pin, 6-pin Tiny SOT23, Pb-Free"
U15: "Infrared Thermopile Sensor with Integrated Math Engine, YZF0008AEAE"
U16: "Digital Pressure Sensor, LGA8-2X2_5MM_0_65"
U17: "10-Bit Micro Power Digital-to-Analog Converter with an I2C-Compatible Interface, 6-pin Tiny SOT23"
U18: "Precision, 20 MHz, 0.9 pA Ib, RRIO, CMOS Operational Amplifier, 1.8 to 5.5 V, -40 to 125 degC, 5-pin SOT23 (DBV0005A), Green (RoHS & no Sb/Br)"
U19: library part OPT3001DNP, "Ambient Light Sensor, DNP0006A"
U20: library part TMP102AIDRL, "Low Power Digital Temperature Sensor With SMBus/Two-Wire Serial Interface in SOT563, DRL0006A"
U21: "IC, SWITCH, SPDT, SOT23-6"
U22 U23: "SINGLE SCHMITT-TRIGGER BUFFER, DCK0005A (SOT-5)"
ZZ1: library part AssemblyNoteLabel
ZZ2 ZZ3 ZZ4: library part AssemblyNote

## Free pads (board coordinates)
  rect 0x0 hole 65 square unplated mask+5: 2(1802.09,890.17) 2(2197.93,890.17)

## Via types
v1: diameter 24, hole 12, Top Layer to Bottom Layer, tented both sides, 177 vias
v2: diameter 32, hole 16, Top Layer to Bottom Layer, tented both sides, 8 vias
v3: diameter 19.68, hole 7.87, Top Layer to Bottom Layer, 7 vias

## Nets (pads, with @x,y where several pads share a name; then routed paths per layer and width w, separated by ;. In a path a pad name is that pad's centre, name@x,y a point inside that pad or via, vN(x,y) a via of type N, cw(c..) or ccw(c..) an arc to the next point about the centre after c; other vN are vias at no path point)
+3.3V: C2.1 C4.1 C8.1 C13.2 C14.2 C15.2 C16.2 C20.2 C21.2 C32.1 C33.2 C34.2 D1.1 J1.2 J4.1 J5.1 R1.2 R2.1 R3.2 R4.2 R5.2 R6.2 R7.2 R12.2 R19.1 R24.2 R36.2 R44.2 R49.1 R67.2 R70.2 R71.2 R74.2 R75.2 R76.2 R77.2 R83.2 R84.2 R87.1 R88.1 R90.2 R91.2 R98.2 R99.2 R100.1 R106.1 R114.2 TP2.1 U1.5 U4.8 U7.5 U8.8 U9.5 U10.5 U13.8 U14.5 U16.2 U16.5 U21.5 U22.5 U23.5 | length 19569.6
  Top Layer w12: 2930,1170 2937.01,1162.99 U16.5@2978.82,1162.99 2978.82,1141.18 2990,1130 3020,1130 3030,1120 U16.2@3030,1100 3030,1075 3040,1065 3075,1065 3100,1040
  Top Layer w15: U7.5@787.6,209.41 790,207.01 790,138.5 C13.2@793.5,135 ; U8.8@2181.85,1340 v1(2210,1340) 2251.5,1340 C14.2@2255,1343.5 ; U22.5@2235.59,1137.2 2257.2,1137.2 2268.5,1148.5 C33.2@2305,1148.5 ; U13.8@2468.39,1340 2541.5,1340 C20.2@2545,1343.5 ; U14.5@2500.59,1137.2 2522.2,1137.2 2533.5,1148.5 C21.2@2575,1148.5 ; C34.2@2766.5,1305 2769.29,1302.2 U23.5@2769.29,1235.59 ; C15.2@2766.5,1544.93 2766.5,1498.5 2769.29,1495.71 U9.5@2769.29,1465.59
  Top Layer w20: U21.5@262.24,850 300,850 310,860 310,880 320,890 C32.1@355,890 ; C8.1@346.5,1535 347.36,1535.87 U4.8@347.36,1613.5 ; U10.5@539.45,909.13 539.45,989.45 C16.2@540,990 ; v1(753.5,135) C13.2@793.5,135 ; R12.2@996.5,340 1200,340 1231,309 1231,207 1255,183 1502,183 J1.2@1550,135 ; v1(1160,1335) R44.2@1160,1523.5 ; C21.2@2575,1148.5 2608.5,1148.5 ; v1(2588.5,1343.5) 2620,1312.01 2620,1160 2608.5,1148.5 ; R70.2@2796.51,820 2796.51,849.7 2811.81,865 2910,865 2950,825 3190,825 3230,865 3230,1020 3210,1040 ; 2930,1170 2905,1195 ; R83.2@2983.5,1320 2927,1320 2905,1298 2905,1195 ; 3100,1040 3210,1040 ; J4.1@3255,1495 3255,1230 3275,1210 3275,1115 3258.5,1098.5 R2.1@3225,1098.5 3225,1055 3210,1040 ; 2608.5,1148.5 2621,1136.01 2621,1115 2632,1104 2814,1104 2905,1195
  Top Layer w25: v1(153.5,1533.5) 153.5,1511.5 180,1485 ; J5.1@155,510 247.01,510 268.5,488.5 ; R49.1@253.35,1250 175,1250 ; R87.1@268.5,405 268.5,488.5 ; v1(320,685) 400,765 400,875 388.5,886.5 C32.1@355,886.5 ; C8.1@346.5,1535 346.5,1497.5 ; C32.1@355,890 355,965 330,990 330,1020 308.5,1041.5 R100.1@255,1041.5 255,1090 ; 445,1110 485,1070 485,1005 500,990 C16.2@540,990 ; R3.2@451.5,1855 501.5,1905 727,1905 772,1860 ; v1@539.56,529.56 v1(539.12,530) v1(355,530) 310,530 268.5,488.5 ; v1(610,530) 640,500 v1(990,500) ; R24.2@620,1052.99 620,1120 ; v1(665,1140) 640,1140 620,1120 ; v1(850,1140) 850,1205 915,1270 v1(1160,1270) 1425,1270 1521.5,1366.5 R106.1@1521.5,1445 ; v1(930,1140) 985,1140 1015,1110 ; v1(990,395) 996.5,388.5 R12.2@996.5,340 ; R71.2@1048.35,1580 1048.35,1543.35 1015,1510 910,1510 810,1410 R67.2@691.34,1410 691.34,1463 668.34,1486 ; v1(1110.83,959.17) 1045,959.17 1015,989.17 1015,1110 ; R75.2@1563.5,1860 1563.5,1898.5 ; R114.2@1768.5,1505 1768.5,1474.5 1831,1412 v1(1831,1375) 1765,1375 1530,1140 1040,1140 1015,1115 1015,1110 ; v1(2074.09,670.91) 2115,630 2175,630 2195,650 ; R77.2@2178.5,1840 2178.5,1886.5 ; R98.2@2286.65,770.75 2235.75,770.75 2195,730 2195,650 ; C33.2@2305,1148.5 v1(2348.5,1148.5) ; R99.2@2380,315 2387.24,307.76 U1.5@2387.24,227.4 2479.09,227.4 C4.1@2485,221.5 2485,225 2543.5,283.5 C2.1@2645,283.5 2706.5,283.5 2765.53,224.47 D1.1@2810,224.47 ; C20.2@2545,1343.5 v1(2588.5,1343.5) ; R84.2@2708.5,900 2708.5,836.5 2725,820 ; C34.2@2766.5,1305 v1(2766.5,1350) ; C15.2@2766.5,1544.93 2766.5,1823.5 2720.75,1869.25 ; R70.2@2796.51,820 2725,820 ; R88.1@2928.35,1870 2928.35,1899.7 2913.05,1915 2770,1915 2724.25,1869.25 2720.75,1869.25 ; R36.2@2963.01,429.97 2963.01,319.51 R1.2@2935,291.5 2891.5,291.5 2875,275 2875,240 2859.47,224.47 D1.1@2810,224.47 ; 175,1250 150,1225 150,1125 165,1110 235,1110 255,1090 ; 175,1250 150,1275 150,1455 180,1485 ; 180,1485 334,1485 346.5,1497.5 ; 255,1090 275,1110 440,1110 470,1140 600,1140 620,1120 ; 346.5,1497.5 357.99,1486 668.34,1486 ; 668.34,1486 690,1507.66 690,1570 741.5,1621.5 R5.2@741.5,1655 R4.2@741.5,1725 741.5,1829.5 772,1860 ; 772,1860 R19.1@850.35,1860 850.35,1900.35 865,1915 1547.01,1915 1563.5,1898.5 ; 1563.5,1898.5 1580,1915 2150,1915 2178.5,1886.5 ; 2178.5,1886.5 2207.01,1915 2615,1915 2660.75,1869.25 2720.75,1869.25 ; 2195,650 2214.32,630.68 R90.2@2286.65,630.68 2286.65,543.35 2440,390 2595,390 2625,420 TP2.1@2705,420 ; TP2.1@2705,420 2705,470 2620,555 2620,630 2636.5,646.5 R91.2@2636.5,680 2665,680 2710,725 2710,805 2725,820 ; TP2.1@2705,420 2765,420 2810,375 D1.1@2810,224.47
  Bottom Layer w20: v1(1160,1270) v1(1160,1335)
  Bottom Layer w25: v1(153.5,1533.5) R6.2@153.5,1655 R7.2@153.5,1725 ; v1(320,685) 320,565 v1(355,530) ; v1(539.12,530) v1(610,530) ; v1(665,1140) v1(850,1140) v1(930,1140) ; v1(753.5,135) 753.5,343.5 805,395 v1(990,395) v1(990,500) ; v1(1110.83,959.17) R74.2@1159.09,959.17 ; v1(1831,1375) 2175,1375 v1(2210,1340) 2457,1340 2494,1303 ; v1(2074.09,670.91) R76.2@2074.09,728.5 ; v1(2348.5,1148.5) 2461.5,1148.5 2494,1181 2494,1303 ; v1(2766.5,1350) 2723.5,1307 2625.01,1307 v1(2588.5,1343.5) 2534.5,1343.5 2494,1303
ALERT_1: U5.4 U8.5 | length 2755.1
  Top Layer w10: U5.4@418.5,175 418.5,146.5 430,135 655,135 723,203 723,383 765,425 1560,425 1680,545 1680,1170 1790,1280 v1(1900,1280) ; v1(2095,1255) 2095,1299.7 2105.08,1309.78 U8.5@2105.08,1340
  Bottom Layer w10: v1(1900,1280) 2070,1280 v1(2095,1255)
ALERT_2: U5.6 U8.6 | length 2468.6
  Top Layer w10: U5.6@633.07,225 685,225 702,242 702,390.28 756.72,445 1545,445 1660,560 1660,1185 1790,1315 v1(1940,1315) ; v1(2130.67,1285.67) U8.6@2130.67,1340
  Bottom Layer w10: v1(1940,1315) 2101.34,1315 v1(2130.67,1285.67)
ALERT_3: U6.4 U8.1 | length 853.8
  Top Layer w10: U8.1@2181.85,1495.51 2181.85,1546.85 2247.13,1612.13 v1(2707.13,1612.13)
  Bottom Layer w10: v1(2707.13,1612.13) 2812.13,1612.13 2890,1690 U6.4@2925,1690
ALERT_4: U6.6 U8.2 | length 691
  Top Layer w10: U8.2@2156.26,1495.51 2156.26,1556.26 2235,1635 2565,1635 v1(2645,1715)
  Bottom Layer w10: v1(2645,1715) 2670,1740 U6.6@2710.43,1740
DC_IN: C1.1 C3.1 J1.5 R99.1 TP1.1 U1.1 U1.3 | length 952.5
  Top Layer w20: C3.1@2185,221.5 2213.5,221.5 2230,205 ; U1.3@2292.76,152.6 2247.4,152.6 2230,170 2230,205 ; U1.1@2292.76,227.4 2252.4,227.4 2230,205 ; R99.1@2292.76,312.76 R99.1@2300,320
  Top Layer w25: U1.1@2292.76,227.4 R99.1@2292.76,312.76
  Top Layer w30: J1.5@1750,225 J1.5@1750,235 1808.5,293.5 C1.1@2015,293.5 2091.5,293.5 2110,275 2110,240 2128.5,221.5 C3.1@2185,221.5 TP1.1@2185,330
GND: C1.2 C2.2 C3.2 C4.2 C5.1 C6.2 C7.1 C8.2 C9.2 C10.2 C11.1 C12.1 C13.1 C14.1 C15.1 C16.1 C17.1 C18.1 C19.1 C20.1 C21.1 C22.1 C23.1 C24.1 C26.1 C27.2 C28.1 C29.2 C30.2 C31.1 C32.2 C33.1 C34.1 C35.1 C37.2 C38.2 D1.2 D2.2 D5.1 J1.6 J2.6 J4.4 J5.4 Q1.4 Q1.7 Q2.4 Q2.7 R32.2 R37.1 R38.1 R50.1 R78.2 R79.2 R93.2 R101.1 R105.2 R111.1 R112.2 R113.1 TP6.1 U1.2 U2.2 U2.5 U3.2 U3.7 U4.4 U5.5 U6.5 U7.2 U7.3 U8.4 U9.3 U10.2 U11.3 U11.8 U12.2 U13.4 U14.3 U15.A1 U15.A2 U16.1 U16.7 U17.3 U18.2 U19.2 U19.3 U19.7 U20.2 U21.2 U22.3 U23.3 | length 5396.5
  Top Layer w10: U19.2@2037.4,890 v3(2000,890) 2000,900 2015.79,915.79 U19.3@2037.4,915.79 2064.21,915.79 2074.09,925.67 v1(2074.09,974.09) ; U20.2@2494.13,660 2525,660 v1(2550,635)
  Top Layer w12: U16.7@3030,1162.99 v1(3030,1200) ; U16.1@3055.59,1100 v1(3095,1100)
  Top Layer w15: U7.2@862.4,235 U7.3@862.4,260.59 v1(862.4,292.6) ; U2.2@930,1665.71 930,1635 v1(945,1620) ; U2.5@930,1754.29 930,1793 v1(939,1802) ; v1(2068.98,1495.51) U8.4@2105.08,1495.51 ; U22.3@2184.41,1225.79 2184.41,1195.59 2195,1185 2248.8,1185 2275.3,1211.5 C33.1@2305,1211.5 ; v1(2355.51,1495.51) U13.4@2391.61,1495.51 ; U3.2@2370,1665.2 v3(2370,1700.63) U3.7@2370,1720.32 ; U14.3@2449.41,1225.79 2449.41,1190.59 2460,1180 2515,1180 2546.5,1211.5 C21.1@2575,1211.5 ; v1(2680.71,1145.71) U23.3@2680.71,1184.41 ; v1(2680.71,1385) U9.3@2680.71,1414.41 ; Q2.7@2738.78,989.41 Q2.4@2771.32,989.41 v1(2771.32,956.32) ; v1(2989.41,1375.59) Q1.4@2989.41,1408.68 Q1.7@2989.41,1441.22 ; C23.1@2991.5,735 2994.51,731.99 v2(2994.51,679.97)
  Top Layer w20: v1(120,850) U21.2@167.76,850 ; U4.4@536.34,1763.5 v1(536.34,1803.66) ; v1(576.85,755) U10.2@576.85,800.87 ; v1(580,175) U5.5@633.07,175 ; C13.1@856.5,135 v1(856.5,175) ; v1(1230,1475) C35.1@1230,1523.5 ; v1(1330,1545) 1345,1530 U18.2@1345,1495.87 ; C38.2@1455,1581.5 v1(1455,1630) ; R111.1@1525,1581.5 v1(1525,1630) ; C19.1@1630,1683.5 1663.5,1683.5 1695.98,1715.98 U12.2@1725.51,1715.98 ; v1(2275,1280) R113.1@2323.5,1280 ; R112.2@2320,1406.5 v1(2364.49,1406.5) ; R38.1@3201,714.97 v1(3201,755) ; R37.1@3202.5,504.97 v1(3247.5,504.97)
  Top Layer w25: v1(131.5,1041.5) R101.1@180,1041.5 ; v1(205,1180) R50.1@253.5,1180 ; v1(240.5,1535) C8.2@283.5,1535 ; v1(265,230.5) C9.2@265,273.5 ; v1(355,775) C32.2@355,823.5 ; v1(492,711.5) C18.1@535,711.5 ; C11.1@500,400 v1(500,443) ; U17.3@527.09,1357.4 v1(527.09,1400.4) ; C16.1@540,1052.99 v1(540,1101.5) ; v1(579.84,1200) C26.1@628.35,1200 ; v1(652,886.5) R105.2@695,886.5 ; C27.2@691.34,1340 v1(734.34,1340) ; C5.1@850.35,1580 v1(850.35,1623) ; v1(1140,840) U11.3@1229.09,840 ; v1(1505,1040) U11.8@1591.3,1040 ; v1(1578,1674) 1587.5,1683.5 C19.1@1630,1683.5 ; v1(1768.5,1547) R32.2@1768.5,1590 ; v1(2185,105) C3.2@2185,158.5 ; v1(2210,1415) 2218.5,1406.5 C14.1@2255,1406.5 ; v1(2235.62,700.62) C31.1@2286.65,700.62 ; v1(2255,80) C6.2@2308.5,80 ; U1.2@2292.76,190 2423,190 2454.5,158.5 C4.2@2485,158.5 v1(2485,105) ; C33.1@2305,1211.5 v1(2348.5,1211.5) ; v1(2305.07,1570.07) R79.2@2353.5,1570.07 ; C7.1@2406.5,1840.32 v1(2451.18,1840.32) ; v1(2494.65,719.65) R93.2@2494.65,770.68 ; C20.1@2545,1406.5 v1(2588.5,1406.5) ; R78.2@2556.5,1570 v1(2604.93,1570) ; C30.2@2575,1051.5 v1(2618.5,1051.5) ; C21.1@2575,1211.5 v1(2575,1255) ; v1(2655.07,1544.93) C15.1@2703.5,1544.93 ; C34.1@2703.5,1305 v1(2703.5,1350) ; D1.2@2809.06,94.59 D1.2@2810,95.53 v1(2854.06,95.53) ; C10.2@2928.35,1735 C12.1@2928.35,1805 v1(3005,1805) ; D2.2@2934.06,95 D2.2@2935,95.94 v1(2979.06,95.94) ; C29.2@2976.5,1545 v1(3024.93,1545) ; C22.1@3046.5,1265 v1(3100,1265) ; v1(3095,1100) 3096.5,1098.5 C24.1@3155,1098.5
  Top Layer w30: J1.6@1750,125 1760,125 1778.5,106.5 C1.2@2015,106.5 ; v1(2105,80) 2041.5,80 C1.2@2015,106.5 ; v1(2105,135) 2043.5,135 C1.2@2015,106.5 ; v1(2735,70) 2671.5,70 C2.2@2645,96.5 2673.5,125 v1(2735,125)
  Bottom Layer w6: 2994.51,615.97 U15.A2@2994.51,634.65 v2(2994.51,679.97) ; U15.A1@3014.19,634.65 3014.19,644.19 3024,654 3044,654 3054.51,664.51 v2(3054.51,679.97)
  Bottom Layer w15: v1(2620,1645) 2695,1645 2710.43,1660.43 U6.5@2710.43,1690
  Bottom Layer w25: C17.1@1229.09,959.17 v1(1310,959.17) ; v1(1580,1490) 1580,1557.5 C37.2@1604,1581.5 1604,1576 1651,1529 v1(1651,1490) ; C28.1@2074.09,925.67 v1(2074.09,974.09)
  other v3: 2332.6,1700.63 2407.4,1700.63 2332.6,1740 2370,1740 2407.4,1740
I2C_SCL: R5.1 R17.2 R22.2 R34.2 R46.1 R55.1 R57.1 R62.2 R73.2 R96.2 TP16.1 U4.2 | length 7243.8
  Top Layer w10: v1(95,1655) R73.2@153.5,1655 ; v1(185,1320) R46.1@253.35,1320 ; U4.2@536.34,1663.5 593.5,1663.5 610,1680 v1(635,1680) 653.5,1680 R5.1@678.5,1655 ; R22.2@1116.85,1674.93 1118.07,1674.93 1148.14,1705 1180,1705 v1(1190,1695) ; v1(1755,1070) 1805,1120 1832.19,1120 v1(1874.09,1161.91) ; R34.2@1993.35,1689.93 2019.93,1689.93 2064.93,1734.93 v1(2064.93,1759.93) 2074.69,1769.68 R17.2@2177.01,1769.68 ; R96.2@2499.65,493.5 2500,493.15 v1(2500,440) ; v1(2725,645) 2740,645 ; 2740.03,644.97 R57.1@2796.51,644.97 R57.1@2796.06,644.51 ; R55.1@3003.63,915 3003.63,871.37 v1(3005,870)
  Bottom Layer w10: v1(185,1320) 215,1350 215,1415 95,1535 v1(95,1655) 115,1675 115,1750 135,1770 385,1770 475,1680 v1(635,1680) ; TP16.1@765,1495 635,1625 v1(635,1680) ; v1(1755,1070) 1675,990 1675,565 1830,410 2320,410 2367,457 2483,457 v1(2500,440) 2541.82,440 2725,623.18 v1(2725,645) 2740,660 2740,790 2806,856 2991,856 v1(3005,870) ; R62.2@1874.09,1110.67 v1(1874.09,1161.91) 1849,1187 1771,1187 1699,1259 1699,1595 1754,1650 2015,1650 2035,1670 2035,1705 2064.93,1734.93 v1(2064.93,1759.93) 2064.93,1817.07 2026,1856 1556,1856 1510,1810 1510,1761.72 1458.28,1710 1205,1710 v1(1190,1695) 1162,1723 1162,1768 1145,1785 1005,1785 905,1685 640,1685 v1(635,1680)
